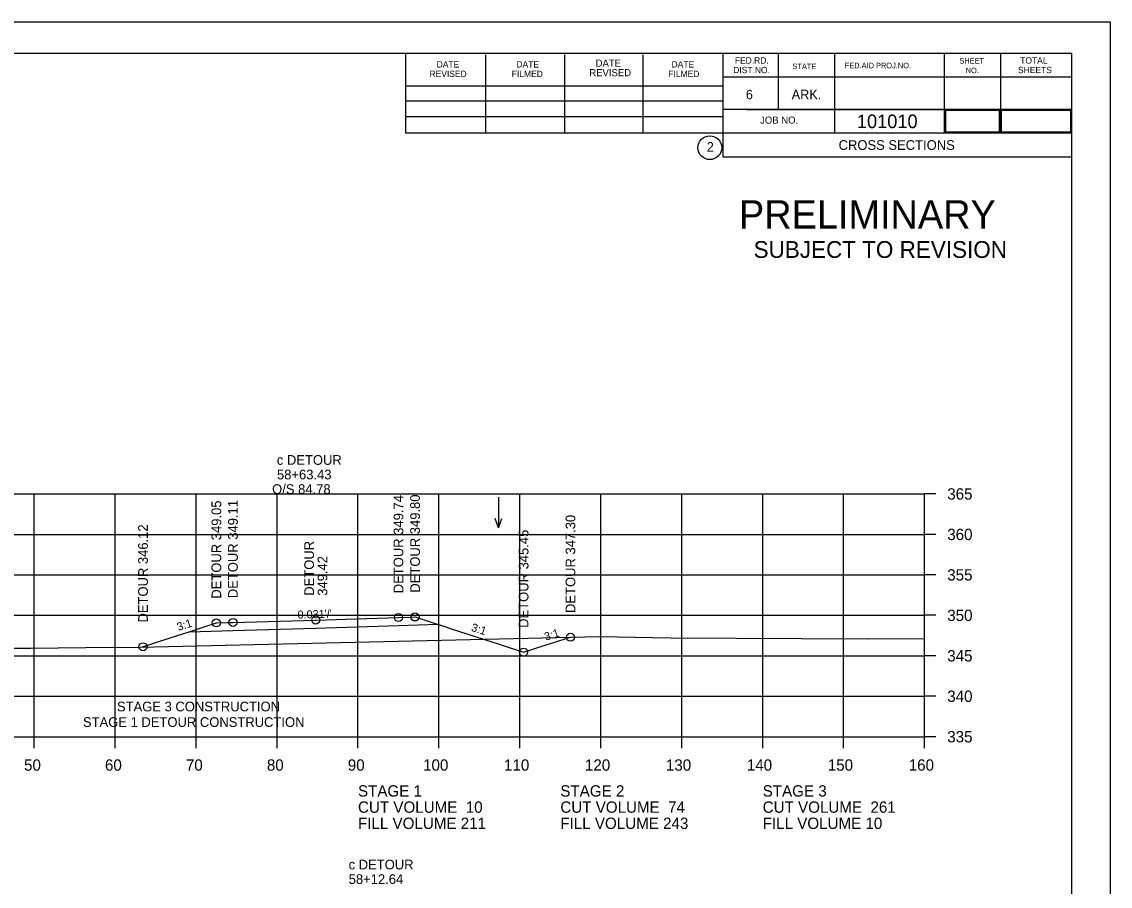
# Model space of a CAD drawing. Extents: x 1630712 to 1632516, y 782146 to 785403.
# Drawn here: x 1632381.4 to 1632515.9, y 784869.8 to 784976.7 of the extents above; entities that cross this region are included whole.
import ezdxf

# ---------------------------------------------------------------- set-up
doc = ezdxf.new("R2010")
doc.units = 0
for name, color, linetype in [('Notes', 7, 'Continuous'), ('Page Number', 7, 'Continuous'), ('R_Axis', 7, 'Continuous'), ('R_Axis Annot', 7, 'Continuous'), ('R_Border', 7, 'Continuous'), ('R_Border Notes', 7, 'Continuous'), ('R_Border Prem', 7, 'Continuous'), ('R_Detour Subgrade', 7, 'Continuous'), ('R_Detour Surface', 7, 'Continuous'), ('R_Exist Surface', 7, 'Continuous'), ('R_Grid', 7, 'Continuous'), ('R_No Plot', 7, 'Continuous'), ('R_Water Annot', 7, 'Continuous'), ('R_Xsect Elev Detour', 7, 'Continuous'), ('R_Xsect Slope', 7, 'Continuous'), ('Total_Pages', 7, 'Continuous')]:
    doc.layers.add(name, color=color, linetype=linetype)

msp = doc.modelspace()

# ---------------------------------------------------------------- linework, layer by layer
at = {"layer": 'Page Number'}
msp.add_lwpolyline([(1632495.54, 784963.04), (1632502.21, 784963.04), (1632502.21, 784965.68), (1632495.54, 784965.68)], close=True, dxfattribs=at)
at = {"layer": 'R_Axis'}
for p, q in [((1632492.96, 784888.31), (1632492.96, 784918.31)), ((1632494.36, 784918.31), (1632492.96, 784918.31)), ((1632494.36, 784913.31), (1632492.96, 784913.31)), ((1632494.36, 784908.31), (1632492.96, 784908.31)), ((1632494.36, 784903.31), (1632492.96, 784903.31)), ((1632494.36, 784898.31), (1632492.96, 784898.31)), ((1632494.36, 784893.31), (1632492.96, 784893.31)), ((1632212.96, 784888.31), (1632492.96, 784888.31)), ((1632382.96, 784886.91), (1632382.96, 784888.31)), ((1632392.96, 784886.91), (1632392.96, 784888.31)), ((1632402.96, 784886.91), (1632402.96, 784888.31)), ((1632412.96, 784886.91), (1632412.96, 784888.31)), ((1632422.96, 784886.91), (1632422.96, 784888.31)), ((1632432.96, 784886.91), (1632432.96, 784888.31)), ((1632442.96, 784886.91), (1632442.96, 784888.31)), ((1632452.96, 784886.91), (1632452.96, 784888.31)), ((1632462.96, 784886.91), (1632462.96, 784888.31)), ((1632472.96, 784886.91), (1632472.96, 784888.31)), ((1632482.96, 784886.91), (1632482.96, 784888.31)), ((1632492.96, 784886.91), (1632492.96, 784888.31)), ((1632494.36, 784888.31), (1632492.96, 784888.31))]:
    msp.add_line(p, q, dxfattribs=at)
at = {"layer": 'R_Border'}
for p, q in [((1632194.96, 784972.77), (1632511.14, 784972.77)), ((1632428.88, 784962.89), (1632428.88, 784972.77)), ((1632438.74, 784962.89), (1632438.74, 784972.57)), ((1632448.5, 784962.89), (1632448.5, 784972.57)), ((1632458.18, 784962.89), (1632458.18, 784972.57)), ((1632468.04, 784972.77), (1632468.04, 784959.97)), ((1632474.88, 784972.77), (1632474.88, 784965.83)), ((1632481.82, 784972.77), (1632481.82, 784962.89)), ((1632495.4, 784972.77), (1632495.4, 784962.89)), ((1632502.34, 784972.77), (1632502.34, 784962.89)), ((1632511.14, 784767.31), (1632511.14, 784972.77)), ((1632511.14, 784969.83), (1632468.04, 784969.83)), ((1632511.14, 784969.85), (1632511.14, 784969.85)), ((1632428.88, 784968.75), (1632468.04, 784968.75)), ((1632428.88, 784966.89), (1632468.04, 784966.89)), ((1632511.14, 784965.83), (1632468.04, 784965.83)), ((1632471, 784965.83), (1632511.14, 784965.83)), ((1632428.88, 784962.89), (1632428.88, 784964.95)), ((1632428.88, 784964.95), (1632468.04, 784964.95)), ((1632511.14, 784962.89), (1632428.88, 784962.89)), ((1632468.04, 784959.97), (1632511.14, 784959.97))]:
    msp.add_line(p, q, dxfattribs=at)
msp.add_circle((1632466.43, 784961.1), 1.47, dxfattribs=at)
at = {"layer": 'R_Detour Subgrade'}
msp.add_lwpolyline([(1632402.09, 784901.27), (1632407.51, 784901.43), (1632417.74, 784901.73), (1632427.96, 784902.04), (1632432.81, 784902.2)], dxfattribs=at)
at = {"layer": 'R_Detour Surface'}
msp.add_lwpolyline([(1632396.33, 784899.4), (1632399.77, 784900.52), (1632402.09, 784901.27), (1632403.95, 784901.88), (1632405.46, 784902.37), (1632406.78, 784902.41), (1632407.51, 784902.43), (1632417.73, 784902.73), (1632417.74, 784902.73), (1632417.74, 784902.73), (1632424.03, 784902.92), (1632427.96, 784903.04), (1632429.39, 784903.09), (1632430.01, 784903.11), (1632432.48, 784902.31), (1632432.81, 784902.2), (1632433.39, 784902.01), (1632433.43, 784902), (1632433.8, 784901.88), (1632434.49, 784901.66), (1632440.53, 784899.69), (1632443.42, 784898.76), (1632446.08, 784899.61), (1632449.21, 784900.6)], dxfattribs=at)
at = {"layer": 'R_Exist Surface'}
msp.add_lwpolyline([(1632373.84, 784899.25), (1632382.54, 784899.26), (1632392.73, 784899.36), (1632394.26, 784899.35), (1632408.37, 784899.66), (1632452.85, 784900.69), (1632461.57, 784900.52), (1632485.86, 784900.42), (1632492.96, 784900.45)], dxfattribs=at)
at = {"layer": 'R_Grid'}
for p, q in [((1632212.96, 784918.31), (1632492.96, 784918.31)), ((1632382.96, 784888.31), (1632382.96, 784918.31)), ((1632392.96, 784888.31), (1632392.96, 784918.31)), ((1632402.96, 784888.31), (1632402.96, 784918.31)), ((1632412.96, 784888.31), (1632412.96, 784918.31)), ((1632422.96, 784888.31), (1632422.96, 784918.31)), ((1632432.96, 784888.31), (1632432.96, 784918.31)), ((1632442.96, 784888.31), (1632442.96, 784918.31)), ((1632452.96, 784888.31), (1632452.96, 784918.31)), ((1632462.96, 784888.31), (1632462.96, 784918.31)), ((1632472.96, 784888.31), (1632472.96, 784918.31)), ((1632482.96, 784888.31), (1632482.96, 784918.31)), ((1632492.96, 784888.31), (1632492.96, 784918.31)), ((1632212.96, 784913.31), (1632492.96, 784913.31)), ((1632212.96, 784908.31), (1632492.96, 784908.31)), ((1632212.96, 784903.31), (1632492.96, 784903.31)), ((1632212.96, 784898.31), (1632492.96, 784898.31)), ((1632212.96, 784893.31), (1632492.96, 784893.31)), ((1632212.96, 784888.31), (1632492.96, 784888.31))]:
    msp.add_line(p, q, dxfattribs=at)
at = {"layer": 'R_No Plot'}
msp.add_line((1632182.56, 784976.66), (1632515.9, 784976.66), dxfattribs=at)
msp.add_lwpolyline([(1632182.56, 784976.66), (1632515.9, 784976.66), (1632515.9, 784763.32), (1632182.56, 784763.32)], close=True, dxfattribs=at)
for centre in [(1632405.46, 784902.37), (1632407.51, 784902.43), (1632417.74, 784902.73), (1632427.96, 784903.04), (1632430.01, 784903.11), (1632396.4, 784899.42), (1632449.21, 784900.6), (1632443.42, 784898.76)]:
    msp.add_circle(centre, 0.5, dxfattribs=at)
at = {"layer": 'R_Water Annot'}
for p, q in [((1632440.31, 784917.91), (1632440.31, 784914.14)), ((1632440.31, 784914.14), (1632439.89, 784915.29)), ((1632440.31, 784914.14), (1632440.73, 784915.29))]:
    msp.add_line(p, q, dxfattribs=at)
at = {"layer": 'Total_Pages'}
msp.add_lwpolyline([(1632502.44, 784963.04), (1632511.05, 784963.04), (1632511.05, 784965.68), (1632502.44, 784965.68)], close=True, dxfattribs=at)

# ---------------------------------------------------------------- texts
at = {"layer": 'Notes'}
for s, p in [('c DETOUR', (1632412.93, 784921.91)), ('58+63.43', (1632412.95, 784920.11)), ('O/S 84.78', (1632412.35, 784918.31)), ('STAGE 3 CONSTRUCTION', (1632393.18, 784891.44)), ('STAGE 1 DETOUR CONSTRUCTION', (1632388.98, 784889.52)), ('c DETOUR', (1632421.8, 784871.91)), ('58+12.64', (1632421.81, 784870.11))]:
    msp.add_text(s, height=1.2, dxfattribs=at).set_placement(p)
at = {"layer": 'R_Axis Annot'}
for s, p in [('365', (1632495.76, 784917.61)), ('360', (1632495.76, 784912.61)), ('355', (1632495.76, 784907.61)), ('350', (1632495.76, 784902.61)), ('345', (1632495.76, 784897.61)), ('340', (1632495.76, 784892.61)), ('335', (1632495.76, 784887.61)), ('50', (1632381.7, 784884.11)), ('60', (1632391.7, 784884.11)), ('70', (1632401.7, 784884.11)), ('80', (1632411.7, 784884.11)), ('90', (1632421.7, 784884.11)), ('100', (1632431, 784884.11)), ('110', (1632441, 784884.11)), ('120', (1632451, 784884.11)), ('130', (1632461, 784884.11)), ('140', (1632471, 784884.11)), ('150', (1632481, 784884.11)), ('160', (1632491, 784884.11)), ('STAGE 1', (1632422.96, 784880.91)), ('STAGE 2', (1632447.96, 784880.91)), ('STAGE 3', (1632472.96, 784880.91)), ('CUT VOLUME  10', (1632422.96, 784878.91)), ('CUT VOLUME  74', (1632447.96, 784878.91)), ('CUT VOLUME  261', (1632472.96, 784878.91)), ('FILL VOLUME 211', (1632422.96, 784876.91)), ('FILL VOLUME 243', (1632447.96, 784876.91)), ('FILL VOLUME 10', (1632472.96, 784876.91))]:
    msp.add_text(s, height=1.4, dxfattribs=at).set_placement(p)
at = {"layer": 'R_Border'}
for s, height, p in [('DATE', 0.782, (1632432.68, 784971.01)), ('DATE', 0.782, (1632442.54, 784971.01)), ('DATE', 0.879, (1632452.32, 784971.11)), ('DATE', 0.782, (1632461.7, 784971.01)), ('DIST.NO.', 0.782, (1632469.32, 784970.31)), ('FED.RD.', 0.782, (1632469.52, 784971.49)), ('STATE', 0.684, (1632476.64, 784970.81)), ('FED.AID PROJ.NO.', 0.684, (1632483.1, 784970.91)), ('SHEET', 0.684, (1632497.26, 784971.49)), ('SHEETS', 0.782, (1632504.5, 784970.31)), ('TOTAL', 0.782, (1632504.78, 784971.49)), ('REVISED', 0.782, (1632431.8, 784969.83)), ('FILMED', 0.782, (1632441.96, 784969.83)), ('REVISED', 0.879, (1632451.54, 784969.93)), ('FILMED', 0.782, (1632461.3, 784969.83)), ('NO.', 0.684, (1632498.04, 784970.31)), ('6', 1.17, (1632470.88, 784967.09)), ('ARK.', 1.172, (1632476.54, 784967.09)), ('JOB NO.', 0.879, (1632472.64, 784964.07)), ('2', 1.17, (1632466.05, 784960.62))]:
    msp.add_text(s, height=height, rotation=360, dxfattribs=at).set_placement(p)
at = {"layer": 'R_Border Notes'}
for s, height, p in [('101010', 1.68, (1632484.6, 784963.52)), ('CROSS SECTIONS', 1.2, (1632482.34, 784960.83))]:
    msp.add_text(s, height=height, dxfattribs=at).set_placement(p)
at = {"layer": 'R_Border Prem'}
for s, height, p in [('PRELIMINARY', 3.5, (1632470.03, 784951.11)), ('SUBJECT TO REVISION', 2.0751, (1632471.84, 784947.48))]:
    msp.add_text(s, height=height, rotation=360, dxfattribs=at).set_placement(p)
at = {"layer": 'R_Xsect Elev Detour'}
for s, p in [('DETOUR 349.05', (1632406.06, 784905.37)), ('DETOUR 349.11', (1632408.11, 784905.43)), ('DETOUR 349.74', (1632428.56, 784906.04)), ('DETOUR 349.80', (1632430.61, 784906.11)), ('DETOUR 347.30', (1632449.81, 784903.6)), ('DETOUR 346.12', (1632397, 784902.42)), ('DETOUR 345.45', (1632444.02, 784901.76)), ('DETOUR', (1632417.52, 784905.73)), ('349.42', (1632419.17, 784905.73))]:
    msp.add_text(s, height=1.2, rotation=90, dxfattribs=at).set_placement(p)
at = {"layer": 'R_Xsect Slope'}
for s, rotation, p in [("0.031'/'", 1.7865, (1632415.51, 784902.89)), ('3:1', 18.0309, (1632400.78, 784901.37)), ('3:1', 342.0231, (1632436.87, 784901.41)), ('3:1', 17.6923, (1632446.16, 784900.16))]:
    msp.add_text(s, height=1, rotation=rotation, dxfattribs=at).set_placement(p)

doc.saveas('drawing.dxf')
